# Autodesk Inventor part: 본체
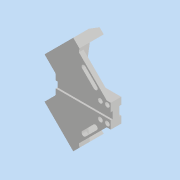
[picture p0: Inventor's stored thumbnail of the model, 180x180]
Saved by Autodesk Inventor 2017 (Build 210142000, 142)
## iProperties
Part Number: 본체
Material: 일반
Document SubType Name: Modeling
Designer: mrc
Density: 1 g/cm^3
Appearance: 기본값
Author: mrc
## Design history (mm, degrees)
sketch "스케치3"
  geometry: L1 (84.853, 0)-(0, 84.853); L2 (0, 84.853)-(-84.853, 0); L3 (-84.853, 0)-(0, -84.853); L4 (0, -84.853)-(84.853, 0); 1 further point
  constraints: 8 end point, 2 horizontal alignment, 2 parallel, 1 perpendicular, 1 vertical alignment
  dimensions: "d10" = 120 distance of L2.end L3.end; "d11" = 120 distance of L1.end L2.end
extrude "돌출2" new body sketch "스케치3" distance "d12" = 18; taper "d13" = 0 deg
sketch "스케치5"
  geometry: L1 (-49.497, 35.355)-(-30.147, 16.005); L2 (-30.147, -16.005)-(-49.497, -35.355); L3 (0, 84.853)-(-84.853, 0) reference; L4 (-84.853, 0)-(0, -84.853) reference; L5 (-49.497, -35.355)-(-84.853, 0); L6 (-84.853, 0)-(-49.497, 35.355); L7 (64.853, -20)-(64.853, 20); L8 (84.853, 0)-(0, 84.853) reference; L9 (0, -84.853)-(84.853, 0) reference; L10 (-30.147, -16.005)-(-30.147, 16.005); L11 (64.853, -20)-(84.853, 0); L12 (64.853, 20)-(84.853, 0); 1 further point
  constraints: 16 end point, 4 collinear, 3 point on line, 2 parallel, 2 vertical
  dimensions: "d14" = 50 distance between parallel lines of L3 L2; "d15" = 50 distance between parallel lines of L1 L4; "d16" = 40 distance of L7.start L7.end; "d18" = 95 distance between parallel lines of L7 L10
extrude "돌출3" cut sketch "스케치5" stored distance "d19" = 18; taper "d20" = 0 deg
sketch "스케치6"
  geometry: L1 (-38.891, -24.749)-(10.607, -74.246); L2 (-49.497, -35.355)-(0, -84.853) reference; L3 (-38.891, 24.749)-(10.607, 74.246); L4 (0, 84.853)-(-49.497, 35.355) reference; L5 (-49.497, 35.355)-(-30.147, 16.005) reference; L6 (-30.147, -16.005)-(-49.497, -35.355) reference; L7 (64.853, 20)-(0, 84.853) reference; L8 (0, -84.853)-(64.853, -20) reference; L9 (10.607, -74.246)-(0, -84.853); L10 (-49.497, -35.355)-(0, -84.853); L11 (-49.497, -35.355)-(-38.891, -24.749); L12 (-38.891, 24.749)-(-49.497, 35.355); L13 (-49.497, 35.355)-(0, 84.853); L14 (0, 84.853)-(10.607, 74.246); L15 (64.853, 20)-(0, 84.853) reference; 1 further point
  constraints: 16 end point, 4 collinear, 2 parallel, 2 point on line
  dimensions: "d21" = 15 distance between parallel lines of L1 L2; "d22" = 15 distance between parallel lines of L3 L4
extrude "돌출4" join sketch "스케치6" distance "d23" = 24; taper "d24" = 0 deg
sketch "스케치7"
  geometry: L1 (10.607, -74.246)-(64.853, -20) reference; L2 (64.853, 20)-(10.607, 74.246) reference; L3 (7.071, -70.711)-(57.782, -20); L4 (57.782, 20)-(7.071, 70.711); L5 (-49.497, -35.355)-(0, -84.853) reference; L6 (0, 84.853)-(-49.497, 35.355) reference; L7 (10.607, -74.246)-(-38.891, -24.749) reference; L8 (-38.891, 24.749)-(10.607, 74.246) reference; L9 (64.853, 20)-(64.853, -20) reference; L10 (0, -84.853)-(64.853, -20) reference; L11 (64.853, -20)-(57.782, -20); L12 (64.853, 20)-(0, 84.853) reference; L13 (64.853, 20)-(57.782, 20); L14 (7.071, 70.711)-(10.607, 74.246); L15 (10.607, 74.246)-(64.853, 20); L16 (64.853, -20)-(10.607, -74.246); L17 (10.607, -74.246)-(7.071, -70.711); 1 further point
  constraints: 16 end point, 3 collinear, 2 horizontal, 2 parallel, 1 perpendicular
  dimensions: "d25" = 5 distance between parallel lines of L1 L3; "d26" = 5 distance between parallel lines of L2 L4
extrude "돌출5" cut sketch "스케치7" stored distance "d31" = 24; taper "d32" = 0 deg
sketch "스케치8"
  geometry: L1 (7.071, -70.711)-(57.782, -20) reference; L2 (57.782, -20)-(64.853, -20) reference; L3 (64.853, -20)-(64.853, 20) reference; L4 (64.853, 20)-(57.782, 20) reference; L5 (57.782, 20)-(7.071, 70.711) reference; L6 (7.071, 70.711)-(-38.891, 24.749) reference; L7 (-38.891, 24.749)-(-30.147, 16.005) reference; L8 (-30.147, 16.005)-(-30.147, -16.005) reference; L9 (-30.147, -16.005)-(-38.891, -24.749) reference; L10 (-38.891, -24.749)-(7.071, -70.711) reference; L11 (-38.891, -24.749)-(-49.497, -35.355) reference; L12 (-49.497, -35.355)-(0, -84.853) reference; L13 (0, -84.853)-(10.607, -74.246) reference; L14 (10.607, -74.246)-(-38.891, -24.749) reference; L15 (-38.891, 24.749)-(10.607, 74.246) reference; L16 (10.607, 74.246)-(0, 84.853) reference; L17 (0, 84.853)-(-49.497, 35.355) reference; L18 (-49.497, 35.355)-(-38.891, 24.749) reference; L19 (57.782, -20)-(7.071, -70.711) reference; L20 (57.782, -20)-(36.569, -20); L21 (7.071, -70.711)-(7.071, -49.497); L22 (7.071, -49.497)-(36.569, -20); L23 (7.071, 49.497)-(7.071, 70.711); L24 (57.782, 20)-(36.569, 20); L25 (36.569, 20)-(7.071, 49.497); 1 further point
  constraints: 12 end point, 2 horizontal, 2 parallel
  dimensions: "d35" = 20 distance between parallel lines of L13 L22; "d36" = 30 distance from line of L21.end L12; "d39" = 20 distance between parallel lines of L16 L25; "d40" = 30 distance from line of L23.start L17
extrude "돌출6" cut sketch "스케치8" distance "d41" = 10; taper "d42" = 0 deg
sketch "스케치9"
  geometry: L1 (18.385, -49.497)-(38.184, -29.698); L2 (21.213, -52.326)-(41.012, -32.527); L3 (35.355, -26.87)-(15.556, -46.669); L4 (57.782, -20)-(7.071, -70.711) reference; L5 (-49.497, -35.355)-(0, -84.853) reference; L6 (0, -84.853)-(10.607, -74.246) reference; A1 r 4 centre (18.385, -49.497) between (15.556, -46.669) and (21.213, -52.326); A2 r 4 centre (38.184, -29.698) between (41.012, -32.527) and (35.355, -26.87); 2 further points
  constraints: 8 end point, 4 point on circle, 4 tangent, 2 centre point, 2 parallel, 1 midpoint
  dimensions: "d43" = 38 distance from line of L1.start L5; "d44" = 28 distance of L1.end L1.start; "d45" = 8 distance between parallel lines of L2 L3; "d46" = 12 distance from line of point (28.284, -39.598) L6
extrude "돌출7" cut sketch "스케치9" distance "d47" = 10; taper "d48" = 0 deg
sketch "스케치10"
  geometry: L1 (64.853, 20)-(64.853, -20) reference; C1 r 2.25 at (46.853, -14); 1 further point
  constraints: 1 centre point
  dimensions: "d51" = 4.5 diameter of C1; "d52" = 18 distance from line of L1 C1.centre; "d53" = 14 vertical distance of point (0, 0) C1.centre
extrude "돌출8" cut sketch "스케치10" distance "d54" = 8; taper "d55" = 0 deg
sketch "스케치11"
  geometry: C1 r 4 at (0, 0); C2 r 2.25 at (0, 0) reference; 1 further point
  constraints: 1 centre point, 1 concentric
  dimensions: "d56" = 8 diameter of C1
extrude "돌출9" cut sketch "스케치11" distance "d57" = 10; taper "d58" = 0 deg
sketch "스케치12"
  geometry: L1 (-30.147, -8)-(64.853, -8); L2 (64.853, -8)-(64.853, 8); L3 (64.853, 8)-(-30.147, 8); L4 (-30.147, 8)-(-30.147, -8); L5 (-30.147, -8)-(64.853, 8); L6 (64.853, -8)-(-30.147, 8); L7 (-30.147, 16.005)-(-30.147, -16.005) reference; 3 further points
  constraints: 12 end point, 3 midpoint, 2 parallel, 1 horizontal, 1 horizontal alignment, 1 perpendicular, 1 point on line
  dimensions: "d66" = 16 distance of L2.end L1.end; "d67" = 95 distance between parallel lines of L2 L4
extrude "돌출10" cut sketch "스케치12" distance "d68" = 3.5; taper "d69" = 0 deg
sketch "스케치13"
  geometry: L1 (64.853, -6)-(-30.147, -6); L2 (-30.147, -6)-(-30.147, 6); L3 (-30.147, 6)-(64.853, 6); L4 (64.853, 6)-(64.853, -6); L5 (64.853, -6)-(-30.147, 6); L6 (-30.147, -6)-(64.853, 6); L7 (64.853, -20)-(64.853, 20) reference; 3 further points
  constraints: 12 end point, 3 midpoint, 2 parallel, 1 horizontal, 1 horizontal alignment, 1 perpendicular, 1 point on line
  dimensions: "d70" = 12 distance of L1.end L2.end; "d71" = 95 distance of L1.start L1.end
extrude "돌출11" cut sketch "스케치13" distance "d72" = 3; taper "d73" = 0 deg
chamfer "모따기1" distance "d74" = 5; stored, may be unused: second distance "d75" = 15, angle "d76" = 45 deg
chamfer "모따기2" distance "d77" = 5; stored, may be unused: second distance "d78" = 15, angle "d79" = 45 deg
fillet "모깎기2" dims "d81" = 5
sketch "스케치15"
  geometry: L1 (10.607, -74.246)-(-38.891, -24.749) reference; L2 (-38.891, -24.749)-(-45.962, -31.82) reference; 2 further points
  constraints: 1 other
  dimensions: "d82" = 5 distance from line of L1 point (-17.678, -53.033); "d83" = 35 distance from line of L2 point (-17.678, -53.033)
feature "엠보싱1" sketch "스케치15" dims "d10" = 120, "d11" = 120, "d19" = 18, "d20" = 0, "d84" = 0.5, "d85" = 0
sketch "스케치16"
  geometry: L1 (7.071, -49.497)-(10.607, -74.246); L2 (7.071, -70.711)-(10.607, -74.246) reference; L3 (10.607, -74.246)-(7.071, -70.711); L4 (7.071, -70.711)-(7.071, -49.497) reference; L5 (7.071, -70.711)-(7.071, -49.497); 1 further point
  constraints: 6 end point, 2 collinear
extrude "돌출12" join sketch "스케치16" distance "d86" = 18; taper "d87" = 0 deg
fillet "모깎기3" dims "d88" = 5
node "솔리드2"
pattern_linear "직사각형 패턴1" dims "d61" = 12, "d64" = 28
mirror "미러1"
mirror "미러2"
node "투영된 루프1"
node "투영된 루프2"
node "투영된 루프3"
other parameters: "d17" = 95
